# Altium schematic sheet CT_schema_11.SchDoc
size 277 x 170 mm
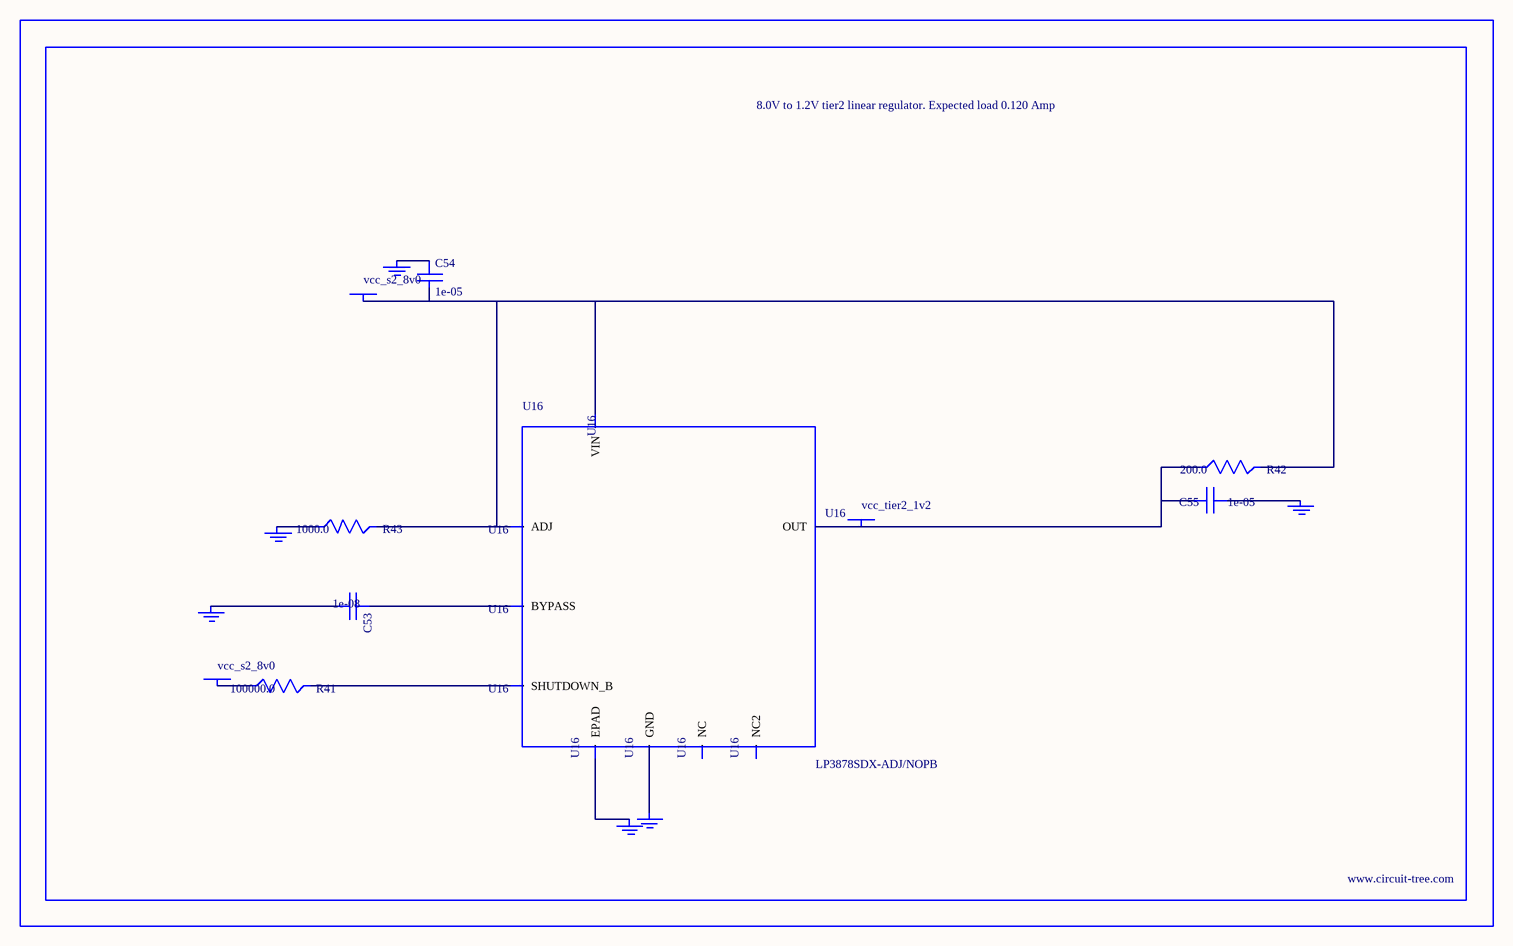
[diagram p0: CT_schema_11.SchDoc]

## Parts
BORDER10  (no value)
C53  1e-08  [C0402]
C54  1e-05  [C1206]
C55  1e-05  [C0805]
GND_INSTANCE_10_0  (no value)
GND_INSTANCE_10_1  (no value)
GND_INSTANCE_10_2  (no value)
GND_INSTANCE_10_3  (no value)
GND_INSTANCE_10_4  (no value)
GND_INSTANCE_10_5  (no value)
POWER_INSTANCE_10_0  vcc_s2_8v0
POWER_INSTANCE_10_1  vcc_s2_8v0
POWER_INSTANCE_10_2  vcc_tier2_1v2
R41  100000.0  [R0603]
R42  200.0  [R0603]
R43  1000.0  [R0603]
U16  LP3878SDX-ADJ/NOPB  [WSON-8]

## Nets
NetC53_1: C53.1 U16.1(BYPASS)
NetC53_2: C53.2 GND_INSTANCE_10_0.0(GND)
NetC54_1: C54.1 GND_INSTANCE_10_1.0(GND)
NetC54_2: C54.2 POWER_INSTANCE_10_0.0(PWR) R42.2 R43.2 U16.4(VIN) U16.6(ADJ)
NetC55_1: C55.1 GND_INSTANCE_10_2.0(GND)
NetC55_2: C55.2 POWER_INSTANCE_10_2.0(PWR) R42.1 U16.5(OUT)
NetGND_INSTANCE_10_3_0: GND_INSTANCE_10_3.0(GND) R43.1
NetGND_INSTANCE_10_4_0: GND_INSTANCE_10_4.0(GND) U16.PAD(EPAD)
NetGND_INSTANCE_10_5_0: GND_INSTANCE_10_5.0(GND) U16.3(GND)
NetPOWER_INSTANCE_10_1_0: POWER_INSTANCE_10_1.0(PWR) R41.1
NetR41_2: R41.2 U16.8(SHUTDOWN_B)

Not connected (* = marked no-connect by the designer): U16 2(NC) 7(NC2)

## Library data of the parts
BORDER10 = BORDER_PAGE10
C53 = C0402C103K3RAC
C54 = C1206C106K3RACTU
C55 = GRM219R60J106ME19D
GND_INSTANCE_10_0-GND_INSTANCE_10_5 = GND
POWER_INSTANCE_10_0-POWER_INSTANCE_10_2 = PWR
R41 = RC0603JR-07100KL
R42 = RC0603JR-07200RL
R43 = RC0603JR-071KL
